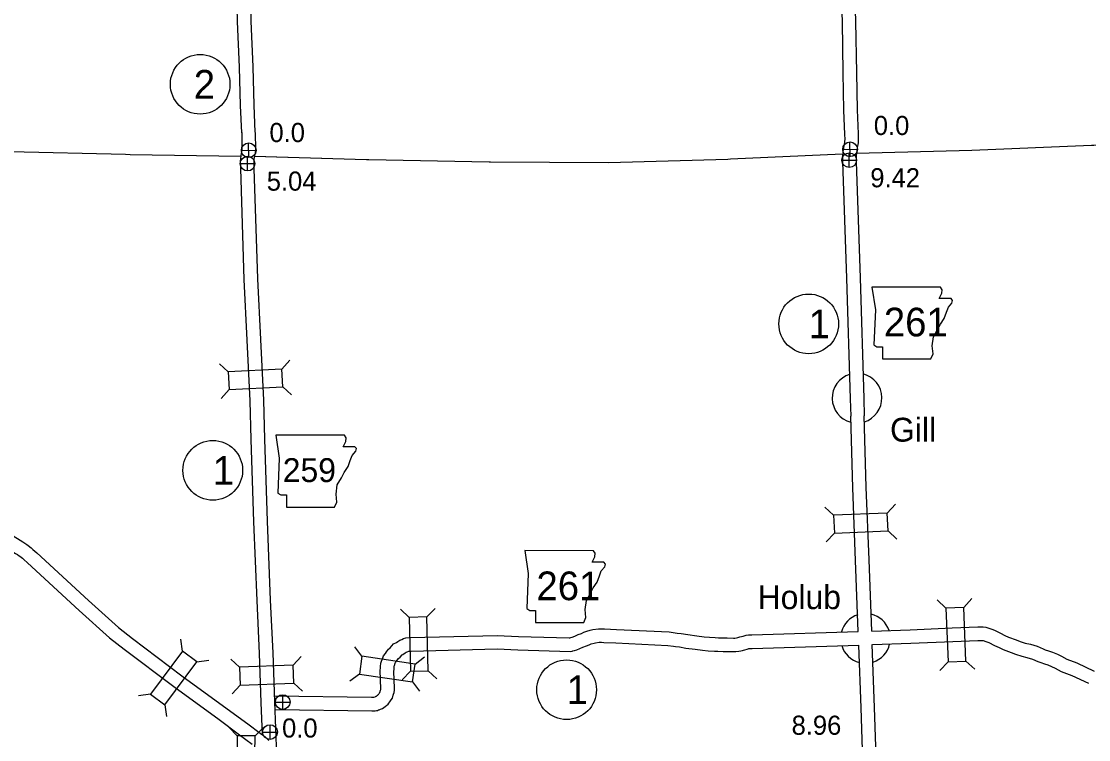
# Model space of a CAD drawing. Extents: x -939622 to -934222, y 1383701 to 1385301.
# Drawn here: x -935897.5 to -935826.6, y 1384217.9 to 1384265.5 of the extents above; entities that cross this region are included whole.
import ezdxf

# ---------------------------------------------------------------- set-up
doc = ezdxf.new("R2010")
doc.units = 0
for name, color, linetype in [('Level 10', 7, 'Continuous'), ('Level 2', 7, 'Continuous'), ('Level 20', 7, 'Continuous'), ('Level 21', 7, 'Continuous'), ('Level 24', 7, 'Continuous'), ('Level 25', 7, 'Continuous'), ('Level 26', 7, 'Continuous'), ('Level 27', 7, 'Continuous')]:
    doc.layers.add(name, color=color, linetype=linetype)

msp = doc.modelspace()

# ---------------------------------------------------------------- linework, layer by layer
at = {"layer": 'Level 10'}
for points in [[(-935843.947, 1384290.421), (-935843.847, 1384287.69), (-935843.655, 1384283.069), (-935843.465, 1384278.902), (-935843.317, 1384275.205), (-935843.182, 1384270.735), (-935843.089, 1384268.417), (-935842.991, 1384265.497), (-935842.938, 1384262.099), (-935842.896, 1384259.622), (-935842.824, 1384258.025)], [(-935843.044, 1384290.358), (-935842.948, 1384287.725), (-935842.756, 1384283.108), (-935842.566, 1384278.94), (-935842.418, 1384275.237), (-935842.283, 1384270.766), (-935842.189, 1384268.45), (-935842.091, 1384265.519), (-935842.038, 1384262.113), (-935841.996, 1384259.65), (-935841.925, 1384258.065)], [(-935881.933, 1384258.175), (-935882.006, 1384259.974), (-935882.077, 1384262.513), (-935882.212, 1384265.547), (-935882.284, 1384268.405), (-935882.363, 1384270.438), (-935882.44, 1384273.105), (-935882.492, 1384275.278), (-935882.526, 1384276.185)], [(-935882.833, 1384258.139), (-935882.905, 1384259.943), (-935882.977, 1384262.48), (-935883.112, 1384265.516), (-935883.183, 1384268.377), (-935883.263, 1384270.408), (-935883.339, 1384273.081), (-935883.37, 1384274.367)], [(-935882.833, 1384258.153), (-935882.824, 1384257.07), (-935882.837, 1384256.973), (-935882.854, 1384256.894), (-935882.876, 1384256.767), (-935882.898, 1384256.606), (-935882.898, 1384256.602)], [(-935881.933, 1384258.161), (-935881.923, 1384257.012), (-935881.95, 1384256.813), (-935881.971, 1384256.722), (-935881.986, 1384256.631), (-935881.991, 1384256.592)], [(-935842.824, 1384258.034), (-935842.816, 1384257.683), (-935842.822, 1384257.582), (-935842.838, 1384257.49), (-935842.87, 1384257.316), (-935842.904, 1384257.098), (-935842.928, 1384256.891), (-935842.937, 1384256.786)], [(-935841.925, 1384258.056), (-935841.915, 1384257.668), (-935841.926, 1384257.479), (-935841.952, 1384257.33), (-935841.983, 1384257.165), (-935842.012, 1384256.978), (-935842.032, 1384256.799), (-935842.034, 1384256.783)], [(-935882.901, 1384256.585), (-935882.898, 1384256.606), (-935882.916, 1384256.432), (-935882.933, 1384256.222), (-935882.924, 1384256.006), (-935882.924, 1384255.758), (-935882.694, 1384248.404), (-935882.3, 1384240.358), (-935882.221, 1384237.788)], [(-935881.993, 1384256.583), (-935882.004, 1384256.497), (-935882.02, 1384256.351), (-935882.031, 1384256.205), (-935882.024, 1384256.024), (-935882.024, 1384255.773), (-935881.794, 1384248.44), (-935881.4, 1384240.393), (-935881.321, 1384237.815)], [(-935882.003, 1384256.58), (-935881.971, 1384256.722)], [(-935842.954, 1384256.729), (-935842.959, 1384256.201), (-935842.684, 1384248.482), (-935842.444, 1384240.489), (-935842.418, 1384239.336)], [(-935842.033, 1384256.784), (-935842.049, 1384256.606), (-935842.057, 1384256.371), (-935842.059, 1384256.212), (-935841.784, 1384248.512), (-935841.544, 1384240.513), (-935841.519, 1384239.356)], [(-935841.918, 1384225.051), (-935842.097, 1384229.765), (-935842.285, 1384234.588), (-935842.418, 1384239.333)], [(-935841.019, 1384225.08), (-935841.198, 1384229.799), (-935841.386, 1384234.618), (-935841.519, 1384239.359)], [(-935904.573, 1384237.32), (-935899.854, 1384232.99), (-935898.379, 1384231.652), (-935898.311, 1384231.593), (-935898.255, 1384231.546), (-935898.192, 1384231.508), (-935897.369, 1384230.993), (-935897.239, 1384230.909), (-935897.092, 1384230.815), (-935897.006, 1384230.748), (-935896.818, 1384230.598), (-935896.704, 1384230.499), (-935896.44, 1384230.261), (-935893.008, 1384227.11), (-935891.021, 1384225.316), (-935890.086, 1384224.585), (-935886.799, 1384222.116), (-935883.796, 1384219.93), (-935882.44, 1384218.92)], [(-935882.221, 1384237.787), (-935882.049, 1384232.33), (-935881.842, 1384227.1), (-935881.68, 1384223.59), (-935881.559, 1384220.34)], [(-935881.321, 1384237.816), (-935881.15, 1384232.362), (-935880.943, 1384227.139), (-935880.781, 1384223.628), (-935880.659, 1384220.375)], [(-935905.181, 1384236.656), (-935900.461, 1384232.325), (-935898.976, 1384230.979), (-935898.897, 1384230.909), (-935898.78, 1384230.811), (-935898.661, 1384230.74), (-935897.853, 1384230.235), (-935897.726, 1384230.152), (-935897.611, 1384230.078), (-935897.562, 1384230.041), (-935897.394, 1384229.906), (-935897.299, 1384229.825), (-935897.046, 1384229.596), (-935893.614, 1384226.444), (-935891.6, 1384224.626), (-935890.634, 1384223.871), (-935887.334, 1384221.393), (-935884.33, 1384219.206), (-935882.978, 1384218.198)], [(-935841.014, 1384225.081), (-935838.468, 1384225.17), (-935835.676, 1384225.289), (-935833.984, 1384225.353), (-935833.625, 1384225.352), (-935833.447, 1384225.331), (-935833.179, 1384225.26), (-935833.039, 1384225.211), (-935832.866, 1384225.132), (-935832.479, 1384224.939), (-935832.179, 1384224.796), (-935831.946, 1384224.682), (-935831.437, 1384224.499), (-935831.168, 1384224.388), (-935830.829, 1384224.28), (-935830.485, 1384224.205), (-935830.046, 1384224.067), (-935829.636, 1384223.894), (-935829.502, 1384223.837), (-935829.286, 1384223.775), (-935829.019, 1384223.687), (-935828.701, 1384223.548), (-935828.416, 1384223.407), (-935828.078, 1384223.213), (-935827.402, 1384222.971), (-935826.251, 1384222.427)], [(-935880.665, 1384220.781), (-935874.211, 1384220.69), (-935874.097, 1384220.694), (-935874.063, 1384220.692), (-935873.987, 1384220.718), (-935873.981, 1384220.72), (-935873.96, 1384220.731), (-935873.916, 1384220.75), (-935873.898, 1384220.759), (-935873.892, 1384220.762), (-935873.874, 1384220.775), (-935873.839, 1384220.806), (-935873.804, 1384220.829), (-935873.794, 1384220.84), (-935873.758, 1384220.881), (-935873.726, 1384220.919), (-935873.71, 1384220.944), (-935873.665, 1384221.016), (-935873.653, 1384221.034), (-935873.636, 1384221.09), (-935873.614, 1384221.157), (-935873.6, 1384221.21), (-935873.597, 1384221.225), (-935873.598, 1384221.248), (-935873.647, 1384222.453), (-935873.621, 1384222.634), (-935873.618, 1384222.733), (-935873.594, 1384222.939), (-935873.547, 1384223.078), (-935873.497, 1384223.233), (-935873.428, 1384223.43), (-935873.301, 1384223.598), (-935873.231, 1384223.693), (-935873.087, 1384223.871), (-935872.974, 1384223.973), (-935872.751, 1384224.239), (-935872.561, 1384224.323), (-935872.476, 1384224.377), (-935872.331, 1384224.477), (-935872.211, 1384224.521), (-935872.093, 1384224.579), (-935871.949, 1384224.633), (-935871.641, 1384224.655), (-935865.871, 1384224.793), (-935864.465, 1384224.724), (-935861.098, 1384224.628), (-935861.09, 1384224.629), (-935861.061, 1384224.636), (-935860.997, 1384224.652), (-935860.91, 1384224.681), (-935860.732, 1384224.751), (-935860.508, 1384224.846), (-935860.289, 1384224.922), (-935860.13, 1384224.998), (-935859.921, 1384225.076), (-935859.706, 1384225.142), (-935859.521, 1384225.194), (-935859.156, 1384225.232), (-935858.937, 1384225.232), (-935858.764, 1384225.222), (-935857.961, 1384225.194), (-935854.47, 1384225.018), (-935854.061, 1384224.959), (-935853.934, 1384224.941), (-935853.664, 1384224.916), (-935853.231, 1384224.845), (-935852.62, 1384224.77), (-935852.145, 1384224.706), (-935851.796, 1384224.674), (-935851.411, 1384224.648), (-935851.192, 1384224.638), (-935850.861, 1384224.62), (-935850.625, 1384224.625), (-935850.196, 1384224.615), (-935850.109, 1384224.618), (-935849.996, 1384224.63), (-935849.914, 1384224.649), (-935849.842, 1384224.666), (-935849.777, 1384224.687), (-935849.672, 1384224.714), (-935849.548, 1384224.747), (-935849.497, 1384224.765), (-935849.354, 1384224.807), (-935849.21, 1384224.822), (-935848.988, 1384224.829), (-935841.918, 1384225.051)], [(-935880.601, 1384219.88), (-935874.202, 1384219.79), (-935874.105, 1384219.793), (-935874.084, 1384219.792), (-935873.971, 1384219.788), (-935873.9, 1384219.806), (-935873.832, 1384219.818), (-935873.762, 1384219.844), (-935873.703, 1384219.864), (-935873.625, 1384219.889), (-935873.564, 1384219.922), (-935873.548, 1384219.929), (-935873.496, 1384219.953), (-935873.408, 1384220.001), (-935873.314, 1384220.07), (-935873.291, 1384220.09), (-935873.215, 1384220.142), (-935873.126, 1384220.236), (-935873.075, 1384220.295), (-935873.003, 1384220.381), (-935872.951, 1384220.46), (-935872.916, 1384220.516), (-935872.831, 1384220.635), (-935872.777, 1384220.822), (-935872.751, 1384220.9), (-935872.722, 1384221.011), (-935872.694, 1384221.153), (-935872.698, 1384221.281), (-935872.745, 1384222.406), (-935872.722, 1384222.558), (-935872.72, 1384222.67), (-935872.711, 1384222.741), (-935872.692, 1384222.797), (-935872.644, 1384222.946), (-935872.626, 1384222.999), (-935872.58, 1384223.059), (-935872.519, 1384223.142), (-935872.432, 1384223.249), (-935872.324, 1384223.347), (-935872.195, 1384223.501), (-935872.136, 1384223.528), (-935871.98, 1384223.626), (-935871.913, 1384223.672), (-935871.855, 1384223.693), (-935871.751, 1384223.745), (-935871.598, 1384223.755), (-935865.883, 1384223.893), (-935864.5, 1384223.825), (-935861.035, 1384223.726), (-935860.912, 1384223.747), (-935860.852, 1384223.761), (-935860.744, 1384223.787), (-935860.599, 1384223.837), (-935860.392, 1384223.918), (-935860.184, 1384224.006), (-935859.946, 1384224.089), (-935859.779, 1384224.168), (-935859.633, 1384224.223), (-935859.451, 1384224.278), (-935859.35, 1384224.307), (-935859.11, 1384224.332), (-935858.963, 1384224.332), (-935858.806, 1384224.323), (-935857.999, 1384224.295), (-935854.557, 1384224.122), (-935854.188, 1384224.068), (-935854.038, 1384224.047), (-935853.778, 1384224.023), (-935853.359, 1384223.954), (-935852.735, 1384223.877), (-935852.246, 1384223.811), (-935851.866, 1384223.777), (-935851.463, 1384223.75), (-935851.238, 1384223.739), (-935850.876, 1384223.719), (-935850.626, 1384223.725), (-935850.191, 1384223.715), (-935850.044, 1384223.719), (-935849.846, 1384223.741), (-935849.713, 1384223.772), (-935849.601, 1384223.797), (-935849.523, 1384223.823), (-935849.444, 1384223.844), (-935849.283, 1384223.886), (-935849.22, 1384223.908), (-935849.18, 1384223.92), (-935849.15, 1384223.923), (-935848.959, 1384223.93), (-935841.884, 1384224.151)], [(-935840.562, 1384185.285), (-935840.825, 1384193.439), (-935841.138, 1384201.357), (-935841.446, 1384211.58), (-935841.729, 1384219.985), (-935841.884, 1384224.151)], [(-935839.662, 1384185.302), (-935839.926, 1384193.471), (-935840.238, 1384201.389), (-935840.546, 1384211.609), (-935840.83, 1384220.017), (-935840.985, 1384224.198)], [(-935840.972, 1384224.182), (-935838.433, 1384224.27), (-935835.639, 1384224.389), (-935833.969, 1384224.453), (-935833.679, 1384224.452), (-935833.616, 1384224.445), (-935833.442, 1384224.398), (-935833.375, 1384224.375), (-935833.256, 1384224.32), (-935832.873, 1384224.13), (-935832.57, 1384223.985), (-935832.297, 1384223.852), (-935831.761, 1384223.659), (-935831.476, 1384223.542), (-935831.063, 1384223.41), (-935830.717, 1384223.334), (-935830.356, 1384223.221), (-935829.986, 1384223.065), (-935829.804, 1384222.988), (-935829.553, 1384222.915), (-935829.341, 1384222.845), (-935829.08, 1384222.732), (-935828.84, 1384222.613), (-935828.457, 1384222.392), (-935827.747, 1384222.138), (-935826.635, 1384221.614)], [(-935881.558, 1384220.34), (-935881.475, 1384218.205)], [(-935880.659, 1384220.375), (-935880.522, 1384216.856)], [(-935882.439, 1384218.919), (-935881.609, 1384218.296), (-935881.392, 1384218.141), (-935881.276, 1384218.061), (-935881.191, 1384217.981), (-935881.117, 1384217.919), (-935881.028, 1384217.826)], [(-935882.979, 1384218.199), (-935882.141, 1384217.57)]]:
    msp.add_lwpolyline(points, dxfattribs=at)
at = {"layer": 'Level 2'}
for points in [[(-935834.366, 1384256.988), (-935826.431, 1384257.306), (-935826.279, 1384257.313), (-935818.486, 1384257.628), (-935818.39, 1384257.624), (-935810.472, 1384257.852), (-935802.691, 1384258.046), (-935802.215, 1384258.056), (-935794.786, 1384258.297), (-935794.208, 1384258.311), (-935790.897, 1384258.388)], [(-935834.366, 1384256.988), (-935826.431, 1384257.306), (-935826.279, 1384257.313), (-935818.486, 1384257.628), (-935818.39, 1384257.624), (-935810.472, 1384257.852), (-935802.691, 1384258.046), (-935802.215, 1384258.056), (-935794.786, 1384258.297), (-935794.208, 1384258.311), (-935790.897, 1384258.388)], [(-935928.617, 1384249.798), (-935928.804, 1384256.042), (-935920.955, 1384256.376), (-935920.706, 1384256.38), (-935912.891, 1384256.785), (-935905.092, 1384257.146), (-935898.323, 1384256.901), (-935898.218, 1384256.901), (-935890.554, 1384256.71), (-935890.238, 1384256.697)], [(-935928.617, 1384249.798), (-935928.804, 1384256.042), (-935920.955, 1384256.376), (-935920.706, 1384256.38), (-935912.891, 1384256.785), (-935905.092, 1384257.146), (-935898.323, 1384256.901), (-935898.218, 1384256.901), (-935890.554, 1384256.71), (-935890.238, 1384256.697)], [(-935890.238, 1384256.697), (-935882.901, 1384256.585)], [(-935890.238, 1384256.697), (-935882.901, 1384256.585)], [(-935882.003, 1384256.58), (-935874.56, 1384256.367), (-935874.392, 1384256.371), (-935866.405, 1384256.198), (-935866.334, 1384256.199), (-935858.497, 1384256.158), (-935850.577, 1384256.375), (-935850.386, 1384256.415), (-935842.954, 1384256.729)], [(-935881.98, 1384256.579), (-935874.56, 1384256.367), (-935874.392, 1384256.371), (-935866.405, 1384256.198), (-935866.334, 1384256.199), (-935858.497, 1384256.158), (-935850.577, 1384256.375), (-935850.386, 1384256.415), (-935842.954, 1384256.729)], [(-935842.033, 1384256.784), (-935834.366, 1384256.988)], [(-935842.033, 1384256.784), (-935834.366, 1384256.988)]]:
    msp.add_lwpolyline(points, dxfattribs=at)
at = {"layer": 'Level 20'}
for p, q in [((-935880.168, 1384242.457), (-935879.636, 1384243.044)), ((-935883.727, 1384242.283), (-935884.314, 1384242.815)), ((-935883.669, 1384241.096), (-935884.201, 1384240.51)), ((-935880.11, 1384241.271), (-935879.523, 1384240.739)), ((-935843.547, 1384232.769), (-935844.129, 1384233.307)), ((-935839.986, 1384232.908), (-935839.448, 1384233.489)), ((-935839.94, 1384231.721), (-935839.358, 1384231.183)), ((-935843.501, 1384231.582), (-935844.039, 1384231.001)), ((-935836.101, 1384226.604), (-935836.683, 1384227.141)), ((-935834.914, 1384226.652), (-935834.377, 1384227.234)), ((-935871.729, 1384225.985), (-935872.302, 1384226.531)), ((-935870.541, 1384226.014), (-935869.995, 1384226.587)), ((-935886.755, 1384223.749), (-935886.867, 1384224.533)), ((-935874.855, 1384223.405), (-935875.328, 1384224.04)), ((-935885.805, 1384223.036), (-935885.021, 1384223.148)), ((-935882.979, 1384222.685), (-935883.559, 1384223.224)), ((-935879.417, 1384222.818), (-935878.879, 1384223.398)), ((-935871.328, 1384222.893), (-935870.693, 1384223.367)), ((-935870.455, 1384222.451), (-935869.882, 1384221.904)), ((-935835.958, 1384223.043), (-935836.495, 1384222.461)), ((-935834.771, 1384223.091), (-935834.188, 1384222.554)), ((-935875.025, 1384222.229), (-935875.66, 1384221.756)), ((-935871.643, 1384222.422), (-935872.189, 1384221.849)), ((-935882.935, 1384221.498), (-935883.474, 1384220.918)), ((-935879.373, 1384221.631), (-935878.793, 1384221.092)), ((-935871.498, 1384221.717), (-935871.025, 1384221.083)), ((-935888.895, 1384220.899), (-935889.679, 1384220.788)), ((-935887.945, 1384220.186), (-935887.834, 1384219.402)), ((-935883.141, 1384218.14), (-935883.694, 1384218.707)), ((-935881.953, 1384218.125), (-935881.386, 1384218.678))]:
    msp.add_line(p, q, dxfattribs=at)
for points in [[(-935880.168, 1384242.457), (-935883.727, 1384242.283), (-935883.669, 1384241.096), (-935880.11, 1384241.271)], [(-935843.501, 1384231.582), (-935839.94, 1384231.721), (-935839.986, 1384232.908), (-935843.547, 1384232.769)], [(-935870.455, 1384222.451), (-935870.541, 1384226.014), (-935871.729, 1384225.985), (-935871.643, 1384222.422)], [(-935834.771, 1384223.091), (-935834.914, 1384226.652), (-935836.101, 1384226.604), (-935835.958, 1384223.043)], [(-935886.755, 1384223.749), (-935888.895, 1384220.899), (-935887.945, 1384220.186), (-935885.805, 1384223.036)], [(-935875.025, 1384222.229), (-935871.498, 1384221.717), (-935871.328, 1384222.893), (-935874.855, 1384223.405)], [(-935882.935, 1384221.498), (-935879.373, 1384221.631), (-935879.417, 1384222.818), (-935882.979, 1384222.685)], [(-935881.998, 1384214.561), (-935881.953, 1384218.125), (-935883.141, 1384218.14), (-935883.186, 1384214.576)]]:
    msp.add_lwpolyline(points, close=True, dxfattribs=at)
at = {"layer": 'Level 21'}
for points in [[(-935841.01, 1384247.901), (-935840.781, 1384246.378), (-935840.883, 1384244.069), (-935840.68, 1384243.942), (-935840.299, 1384243.942), (-935840.299, 1384243.13), (-935837.102, 1384243.13), (-935836.95, 1384243.46), (-935837, 1384243.993), (-935836.924, 1384244.602), (-935836.645, 1384245.084), (-935836.467, 1384245.439), (-935836.214, 1384245.82), (-935836.061, 1384246.226), (-935835.934, 1384246.556), (-935835.706, 1384246.835), (-935835.655, 1384247.013), (-935835.757, 1384247.139), (-935836.544, 1384247.139), (-935836.366, 1384247.495), (-935836.341, 1384247.723), (-935836.446, 1384247.898)], [(-935880.576, 1384238.068), (-935880.347, 1384236.545), (-935880.449, 1384234.236), (-935880.246, 1384234.109), (-935879.865, 1384234.109), (-935879.865, 1384233.297), (-935876.668, 1384233.297), (-935876.516, 1384233.627), (-935876.566, 1384234.16), (-935876.49, 1384234.769), (-935876.211, 1384235.251), (-935876.033, 1384235.606), (-935875.78, 1384235.987), (-935875.627, 1384236.393), (-935875.501, 1384236.723), (-935875.272, 1384237.002), (-935875.221, 1384237.18), (-935875.323, 1384237.307), (-935876.11, 1384237.307), (-935875.932, 1384237.662), (-935875.907, 1384237.89), (-935876.012, 1384238.066)], [(-935864.046, 1384230.413), (-935863.818, 1384228.891), (-935863.919, 1384226.581), (-935863.716, 1384226.454), (-935863.336, 1384226.454), (-935863.336, 1384225.642), (-935860.138, 1384225.642), (-935859.986, 1384225.972), (-935860.037, 1384226.505), (-935859.96, 1384227.114), (-935859.681, 1384227.596), (-935859.504, 1384227.952), (-935859.25, 1384228.332), (-935859.098, 1384228.738), (-935858.971, 1384229.068), (-935858.742, 1384229.347), (-935858.692, 1384229.525), (-935858.793, 1384229.652), (-935859.58, 1384229.652), (-935859.402, 1384230.007), (-935859.377, 1384230.236), (-935859.482, 1384230.411)]]:
    msp.add_lwpolyline(points, close=True, dxfattribs=at)
at = {"layer": 'Level 24'}
for centre, start, end in [((-935841.996, 1384240.533), 107.42223, 255.23288), ((-935841.996, 1384240.533), 287.11974, 75.68201), ((-935841.435, 1384224.596), 108.14559, 165.0686), ((-935841.435, 1384224.596), 18.57926, 76.62866), ((-935841.435, 1384224.596), 196.69926, 255.74295), ((-935841.435, 1384224.596), 287.70971, 346.52217)]:
    msp.add_arc(centre, 1.65, start, end, dxfattribs=at)
at = {"layer": 'Level 26'}
for p, q in [((-935882.369, 1384256.482), (-935882.375, 1384257.458)), ((-935842.458, 1384256.548), (-935842.464, 1384257.525)), ((-935882.86, 1384256.967), (-935881.883, 1384256.973)), ((-935882.448, 1384255.602), (-935882.448, 1384256.577)), ((-935842.949, 1384257.034), (-935841.973, 1384257.039)), ((-935842.514, 1384255.83), (-935842.514, 1384256.805)), ((-935882.935, 1384256.09), (-935881.96, 1384256.09)), ((-935843.001, 1384256.317), (-935842.026, 1384256.317)), ((-935880.601, 1384220.372), (-935879.626, 1384220.372)), ((-935880.113, 1384219.884), (-935880.113, 1384220.859)), ((-935881.446, 1384218.382), (-935880.471, 1384218.382)), ((-935880.958, 1384217.895), (-935880.958, 1384218.87))]:
    msp.add_line(p, q, dxfattribs=at)
for centre, radius in [((-935882.372, 1384256.97), 0.488), ((-935842.461, 1384257.037), 0.488), ((-935882.448, 1384256.09), 0.487), ((-935842.514, 1384256.317), 0.487), ((-935880.113, 1384220.372), 0.487), ((-935880.958, 1384218.382), 0.487)]:
    msp.add_circle(centre, radius, dxfattribs=at)
at = {"layer": 'Level 27'}
for centre in [(-935885.593, 1384261.349), (-935845.205, 1384245.455), (-935884.754, 1384235.741), (-935861.269, 1384221.189)]:
    msp.add_circle(centre, 1.98, dxfattribs=at)

# ---------------------------------------------------------------- texts
at = {"layer": 'Level 21'}
for s, height, p in [('261', 1.9008, (-935840.217, 1384244.627)), ('259', 1.584, (-935880.112, 1384234.963)), ('261', 1.9008, (-935863.274, 1384227.129))]:
    msp.add_text(s, height=height, dxfattribs=at).set_placement(p)
at = {"layer": 'Level 24'}
for s, p in [('Gill', (-935839.804, 1384237.644)), ('Holub', (-935848.595, 1384226.536))]:
    msp.add_text(s, height=1.584, dxfattribs=at).set_placement(p)
at = {"layer": 'Level 25'}
for s, p in [('0.0', (-935840.881, 1384257.983)), ('0.0', (-935880.995, 1384257.517)), ('9.42', (-935841.115, 1384254.517)), ('5.04', (-935881.173, 1384254.294)), ('0.0', (-935880.156, 1384218.016)), ('8.96', (-935846.338, 1384218.2))]:
    msp.add_text(s, height=1.2672, dxfattribs=at).set_placement(p)
at = {"layer": 'Level 27'}
for s, p in [('2', (-935886.018, 1384260.399)), ('1', (-935845.205, 1384244.505)), ('1', (-935884.754, 1384234.791)), ('1', (-935861.269, 1384220.239))]:
    msp.add_text(s, height=1.901, dxfattribs=at).set_placement(p)

doc.saveas('drawing.dxf')
